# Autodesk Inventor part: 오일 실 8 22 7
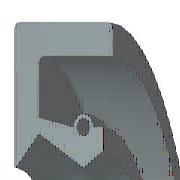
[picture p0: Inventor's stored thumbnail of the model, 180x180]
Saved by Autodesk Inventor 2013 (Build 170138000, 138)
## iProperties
IsCustomPart: 1
Created: 2012-02
Part Number: 오일 실 8 22 7
Material: 고무
Description: 오일-실
Document SubType Name: Modeling
Standard: KS B 2804
Designer: mduedu
Standards Organization: KS
Language: ko-KR
Size Designation: D - 8 22 7
Categories: <MemberInstance><Categories><Category DisplayName="샤프트 부품" InternalName="7f7aeb1f-a693-4053-b835-cee3144e0d98" Mnemonic="SHFT"><Category DisplayName="실링" Intern
Density: 0.93 g/cm^3
Author: mduedu
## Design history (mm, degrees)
revolve "본체" stored, may be unused: angle "d17" = 90 deg
revolve "스프링1" stored, may be unused: angle "d18" = 90 deg
body "Solid1"
sketch "스케치1"
  geometry: L1 (0, 11)-(7, 11); L2 (7, 9.25)-(1.75, 9.25); L3 (1.75, 5.75)-(4.9, 4); L4 (4.9, 4)-(0, 4); L5 (0, 0)-(9.586, 0) reference; L6 (4.9, 4)-(6.3, 4.875); L7 (0, 18)-(0, -3) reference; L8 (-1.941, 0)-(11.507, 0) reference; L9 (4.2, 6.1)-(1.75, 6.59); L10 (1.75, 6.59)-(1.75, 9.25); L11 (0, 11)-(0, 4.088); L12 (4.9, 4)-(0, 4); L13 (1.75, 5.75)-(0.152, 4.028); L14 (7, 11)-(7, 9.25); L15 (5.6, 6.1)-(6.3, 6.1); L16 (6.3, 6.1)-(6.3, 4.875); C1 r 0.455 at (4.9, 6.1); A1 r 0.7 centre (4.9, 6.1) between (5.6, 6.1) and (4.2, 6.1); A2 r 0.088 centre (0.088, 4.088) between (0, 4.088) and (0.152, 4.028); 1 further point
  constraints: 28 end point, 5 horizontal alignment, 5 point on line, 4 point on circle, 4 vertical alignment, 3 centre point, 3 tangent, 2 collinear, 2 horizontal, 2 perpendicular, 1 coincident, 1 parallel
  dimensions: "d0" = 22 diameter of L1 L5 (= SD2); "d1" = 1.75 distance of L1.end L2.start (= SD); "d2" = 0.91 diameter of C1 (= SPDI); "d3" = 1.4 diameter of A1 (= SPDA); "d4" = 8 diameter of L3.end L5 (= NND); "d5" = 11.5 diameter of L3.start L5 (= TKDM); "d7" = 13.18 diameter of L9.end L5 (= TKDM + 0.24 x SWDT); "d8" = 1.75 distance between parallel lines of L11 L10 (= SD); "d9" = 4.9 distance from line of L11 C1.centre (= SPDST); "d10" = 12.2 diameter of C1.centre L5 (= HLDM); "d11" = 0.0875 radius of A2 (= 0.25 x LAB); "d12" = 6.3 distance between parallel lines of L11 L16 (= SDI); "d13" = 9.75 diameter of L6.end L5 (= ABDM); "d14" = 7 distance from line of L11 L1.end (= SWDT)
fillet "모깎기1" dims "d6" = 0.3 (= RR)
other parameters: "SD2" = 22 [user parameter; used in 1 equation term], "SWDT" = 7 [user parameter; used in 2 equation terms], "RR" = 0.3 [user parameter; used in 1 equation term], "SD" = 1.75 [user parameter; used in 2 equation terms], "NND" = 8 [user parameter; used in 1 equation term], "SPDA" = 1.4 [user parameter; used in 1 equation term], "SPDI" = 0.91 [user parameter; used in 1 equation term], "TKDM" = 11.5 [user parameter; used in 2 equation terms], "HLDM" = 12.2 [user parameter; used in 1 equation term], "ABDM" = 9.75 [user parameter; used in 1 equation term], "SDI" = 6.3 [user parameter; used in 1 equation term], "SPDST" = 4.9 [user parameter; used in 1 equation term], "LAB" = 0.35 [user parameter; used in 1 equation term], "d15" = 0, "d16" = 0, "d19" = 0
